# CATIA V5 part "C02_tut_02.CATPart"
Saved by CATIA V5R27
Part number: Part1
Bounding box of the stored display mesh (mm): x 0 to 0, y -60 to 60, z -50 to 50
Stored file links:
  E:\_Deepak\2017_Deepak\CATIA\Resources\Tutorial Files\Tutorials\c02_catia_v5_6r2016_tut\C02_tut_02.CATPart
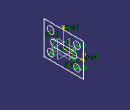
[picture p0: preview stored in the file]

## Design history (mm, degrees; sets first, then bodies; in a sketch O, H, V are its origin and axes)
Body1 (main body)
  Sketch1 on yz-plane, origin (0, 0, 0), H (0, 1, 0), V (0, 0, 1)
    line L1 (60, 50) -> (60, -50)
    line L2 (60, -50) -> (-60, -50)
    line L3 (-60, -50) -> (-60, 50)
    line L4 (-60, 50) -> (60, 50)
    line L5 (-30, 10) -> (30, 10)
    arc A1 centre (30, 0) radius 10 from (30, 10) to (30, -10) cw
    line L6 (30, -10) -> (-30, -10)
    arc A2 centre (-30, 0) radius 10 from (-30, -10) to (-30, 10) cw
    circle A3 centre (40, 30) radius 10
    circle A4 centre (-40, 30) radius 10
    circle A5 centre (40, -30) radius 10
    circle A6 centre (-40, -30) radius 10
    radius A3 = 10
    radius A5 = 10
    radius A6 = 10
    vertical: L1 V, L3 V
    horizontal: L2 H, L4 H, L5 H
    equidistance: L1 L3 O, L2 L4 O
    tangency: A1 L5, L6 A1, A2 L5, A2 L6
